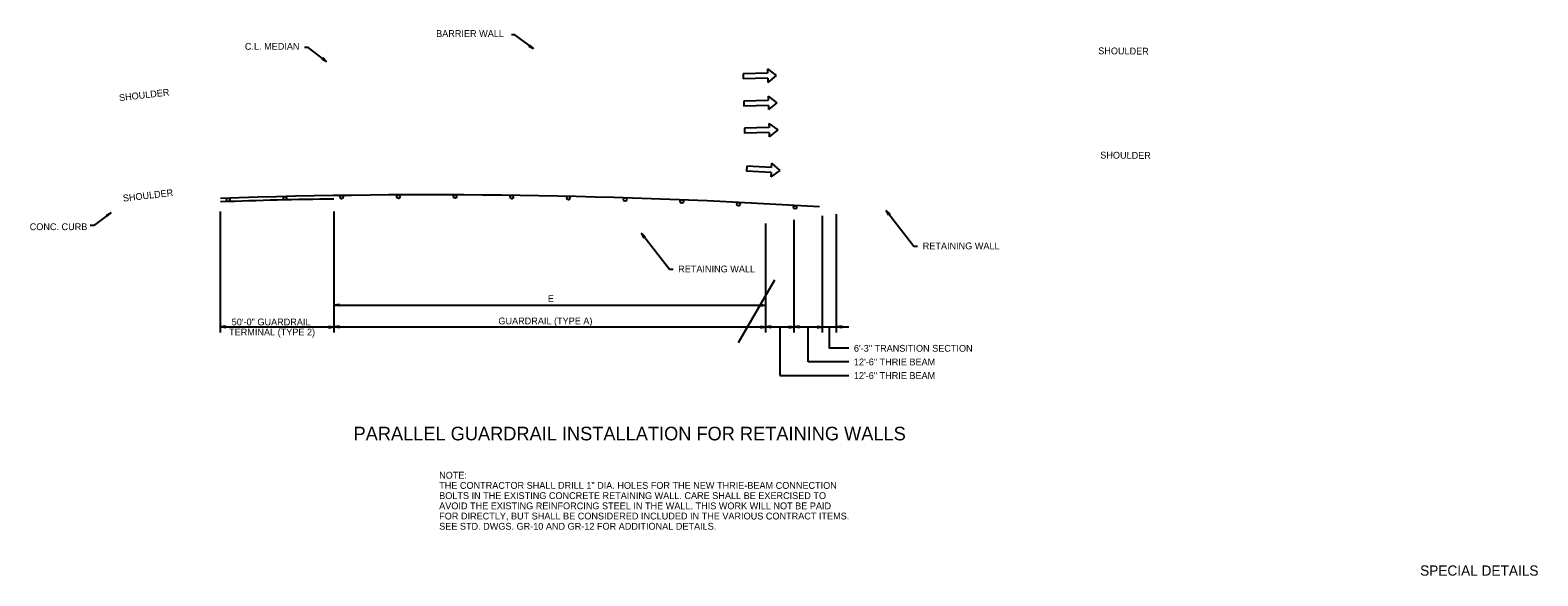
# Model space of a CAD drawing. Extents: x 1373853 to 1374003, y 380191 to 380927.
# Drawn here: x 1373870.3 to 1374003.2, y 380509.2 to 380557.2 of the extents above; entities that cross this region are included whole.
import ezdxf

# ---------------------------------------------------------------- set-up
doc = ezdxf.new("R2010")
doc.units = 0
for name, color, linetype in [('2', 7, 'Continuous'), ('7', 7, 'Continuous'), ('8', 7, 'Continuous'), ('Default', 7, 'Continuous'), ('E_Existing ROW', 7, 'Continuous'), ('G-ANNO-TEXT', 7, 'Continuous'), ('R_Proposed Road', 7, 'Continuous')]:
    doc.layers.add(name, color=color, linetype=linetype)

msp = doc.modelspace()

# ---------------------------------------------------------------- linework, layer by layer
at = {"layer": '2'}
for p, q in [((1373913.01, 380556.85), (1373912.7, 380556.85)), ((1373914.64, 380555.62), (1373913.01, 380556.85)), ((1373894.78, 380555.72), (1373894.46, 380555.72)), ((1373896.4, 380554.49), (1373894.78, 380555.72)), ((1373945.73, 380541.37), (1373948.19, 380538.22)), ((1373875.87, 380540.03), (1373875.55, 380540.03)), ((1373877.41, 380541.19), (1373875.87, 380540.03)), ((1373887.06, 380530.62), (1373887.06, 380541.28)), ((1373897.06, 380530.62), (1373897.06, 380541.28)), ((1373935.12, 380530.62), (1373935.12, 380540.21)), ((1373937.62, 380530.62), (1373937.62, 380540.54)), ((1373940.12, 380530.62), (1373940.12, 380540.88)), ((1373941.37, 380530.62), (1373941.37, 380541.05)), ((1373924.17, 380539.35), (1373926.63, 380536.19)), ((1373948.19, 380538.22), (1373948.51, 380538.22)), ((1373926.63, 380536.19), (1373926.95, 380536.19)), ((1373897.06, 380533.02), (1373935.12, 380533.02)), ((1373887.06, 380531.1), (1373897.06, 380531.1)), ((1373897.06, 380531.1), (1373935.12, 380531.1)), ((1373935.12, 380531.1), (1373937.62, 380531.1)), ((1373936.37, 380531.1), (1373936.37, 380526.81)), ((1373937.62, 380531.1), (1373940.12, 380531.1)), ((1373938.87, 380528.02), (1373938.87, 380531.1)), ((1373940.12, 380531.1), (1373941.37, 380531.1)), ((1373941.37, 380531.1), (1373942.45, 380531.1)), ((1373936.37, 380526.81), (1373942.45, 380526.81)), ((1373942.45, 380528.02), (1373938.87, 380528.02))]:
    msp.add_line(p, q, dxfattribs=at)
msp.add_lwpolyline([(1373942.45, 380529.22), (1373940.75, 380529.22), (1373940.75, 380531.1)], dxfattribs=at)
at = {"layer": '7'}
for p, q in [((1373914.22, 380555.85), (1373914.3, 380555.96)), ((1373914.29, 380555.96), (1373914.58, 380555.67)), ((1373914.3, 380555.96), (1373914.64, 380555.62)), ((1373895.98, 380554.72), (1373896.06, 380554.83)), ((1373895.98, 380554.73), (1373896.34, 380554.54)), ((1373895.98, 380554.72), (1373896.4, 380554.49)), ((1373895.99, 380554.74), (1373896.27, 380554.59)), ((1373896, 380554.75), (1373896.21, 380554.63)), ((1373896.01, 380554.77), (1373896.08, 380554.73)), ((1373896.01, 380554.76), (1373896.15, 380554.68)), ((1373896.03, 380554.79), (1373896.08, 380554.73)), ((1373896.04, 380554.8), (1373896.15, 380554.68)), ((1373896.04, 380554.8), (1373896.21, 380554.63)), ((1373896.05, 380554.82), (1373896.34, 380554.54)), ((1373896.05, 380554.81), (1373896.27, 380554.59)), ((1373896.06, 380554.83), (1373896.4, 380554.49)), ((1373914.22, 380555.86), (1373914.58, 380555.67)), ((1373914.22, 380555.85), (1373914.64, 380555.62)), ((1373914.23, 380555.87), (1373914.51, 380555.72)), ((1373914.24, 380555.88), (1373914.45, 380555.76)), ((1373914.25, 380555.9), (1373914.32, 380555.86)), ((1373914.25, 380555.89), (1373914.38, 380555.81)), ((1373914.27, 380555.93), (1373914.38, 380555.81)), ((1373914.27, 380555.92), (1373914.32, 380555.86)), ((1373914.28, 380555.94), (1373914.51, 380555.72)), ((1373914.28, 380555.93), (1373914.45, 380555.76)), ((1373946.08, 380541.04), (1373945.73, 380541.37)), ((1373945.97, 380540.95), (1373945.73, 380541.37)), ((1373876.99, 380540.96), (1373877.41, 380541.19)), ((1373876.99, 380540.95), (1373877.35, 380541.14)), ((1373876.99, 380540.96), (1373877.07, 380540.85)), ((1373877, 380540.94), (1373877.28, 380541.09)), ((1373877.01, 380540.93), (1373877.22, 380541.05)), ((1373877.02, 380540.92), (1373877.15, 380541)), ((1373877.02, 380540.91), (1373877.09, 380540.95)), ((1373877.04, 380540.88), (1373877.15, 380541)), ((1373877.04, 380540.89), (1373877.09, 380540.95)), ((1373877.05, 380540.87), (1373877.28, 380541.09)), ((1373877.05, 380540.88), (1373877.22, 380541.05)), ((1373877.06, 380540.85), (1373877.35, 380541.14)), ((1373877.07, 380540.85), (1373877.41, 380541.19)), ((1373946.07, 380541.03), (1373945.78, 380541.31)), ((1373945.98, 380540.96), (1373945.78, 380541.31)), ((1373945.99, 380540.97), (1373945.83, 380541.25)), ((1373946.06, 380541.03), (1373945.83, 380541.25)), ((1373946.05, 380541.02), (1373945.88, 380541.18)), ((1373946, 380540.98), (1373945.88, 380541.18)), ((1373946, 380540.98), (1373945.92, 380541.12)), ((1373946.04, 380541.01), (1373945.92, 380541.12)), ((1373946.08, 380541.04), (1373945.97, 380540.95)), ((1373946.01, 380540.99), (1373945.98, 380541.06)), ((1373946.03, 380541), (1373945.98, 380541.06)), ((1373924.52, 380539.02), (1373924.17, 380539.35)), ((1373924.41, 380538.93), (1373924.17, 380539.35)), ((1373924.51, 380539.01), (1373924.22, 380539.29)), ((1373924.42, 380538.93), (1373924.22, 380539.29)), ((1373924.43, 380538.94), (1373924.27, 380539.22)), ((1373924.5, 380539), (1373924.27, 380539.22)), ((1373924.49, 380538.99), (1373924.32, 380539.16)), ((1373924.44, 380538.95), (1373924.32, 380539.16)), ((1373924.44, 380538.96), (1373924.37, 380539.1)), ((1373924.48, 380538.99), (1373924.37, 380539.1)), ((1373924.52, 380539.02), (1373924.41, 380538.93)), ((1373924.45, 380538.97), (1373924.42, 380539.03)), ((1373924.47, 380538.98), (1373924.42, 380539.03)), ((1373897.53, 380533.09), (1373897.06, 380533.02)), ((1373897.53, 380532.95), (1373897.06, 380533.02)), ((1373897.53, 380533.08), (1373897.13, 380533.02)), ((1373897.53, 380532.96), (1373897.13, 380533.02)), ((1373897.53, 380533.07), (1373897.22, 380533.02)), ((1373897.53, 380532.97), (1373897.22, 380533.02)), ((1373897.53, 380533.06), (1373897.3, 380533.02)), ((1373897.53, 380532.98), (1373897.3, 380533.02)), ((1373897.53, 380533.04), (1373897.38, 380533.02)), ((1373897.53, 380533), (1373897.38, 380533.02)), ((1373897.53, 380533.03), (1373897.46, 380533.02)), ((1373897.53, 380533.01), (1373897.46, 380533.02)), ((1373897.53, 380532.95), (1373897.53, 380533.09)), ((1373934.64, 380533.09), (1373935.12, 380533.02)), ((1373934.64, 380533.09), (1373934.64, 380532.95)), ((1373934.64, 380533.08), (1373935.04, 380533.02)), ((1373934.64, 380533.07), (1373934.96, 380533.02)), ((1373934.64, 380533.06), (1373934.88, 380533.02)), ((1373934.64, 380533.04), (1373934.8, 380533.02)), ((1373934.64, 380533.03), (1373934.72, 380533.02)), ((1373934.64, 380532.95), (1373935.12, 380533.02)), ((1373934.64, 380533), (1373934.8, 380533.02)), ((1373934.64, 380532.97), (1373934.96, 380533.02)), ((1373934.64, 380532.96), (1373935.04, 380533.02)), ((1373934.64, 380532.98), (1373934.88, 380533.02)), ((1373934.64, 380533.01), (1373934.72, 380533.02)), ((1373887.53, 380531.17), (1373887.06, 380531.1)), ((1373887.53, 380531.02), (1373887.06, 380531.1)), ((1373887.53, 380531.16), (1373887.13, 380531.1)), ((1373887.53, 380531.04), (1373887.13, 380531.1)), ((1373887.53, 380531.14), (1373887.22, 380531.1)), ((1373887.53, 380531.05), (1373887.22, 380531.1)), ((1373887.53, 380531.13), (1373887.3, 380531.1)), ((1373887.53, 380531.06), (1373887.3, 380531.1)), ((1373887.53, 380531.12), (1373887.38, 380531.1)), ((1373887.53, 380531.07), (1373887.38, 380531.1)), ((1373887.53, 380531.11), (1373887.46, 380531.1)), ((1373887.53, 380531.08), (1373887.46, 380531.1)), ((1373887.53, 380531.02), (1373887.53, 380531.17)), ((1373896.58, 380531.17), (1373897.06, 380531.1)), ((1373896.58, 380531.17), (1373896.58, 380531.02)), ((1373896.58, 380531.16), (1373896.97, 380531.1)), ((1373896.58, 380531.14), (1373896.89, 380531.1)), ((1373896.58, 380531.13), (1373896.81, 380531.1)), ((1373896.58, 380531.12), (1373896.73, 380531.1)), ((1373896.58, 380531.11), (1373896.65, 380531.1)), ((1373896.58, 380531.02), (1373897.06, 380531.1)), ((1373896.58, 380531.07), (1373896.73, 380531.1)), ((1373896.58, 380531.05), (1373896.89, 380531.1)), ((1373896.58, 380531.04), (1373896.97, 380531.1)), ((1373896.58, 380531.06), (1373896.81, 380531.1)), ((1373896.58, 380531.08), (1373896.65, 380531.1)), ((1373897.53, 380531.17), (1373897.06, 380531.1)), ((1373897.53, 380531.02), (1373897.06, 380531.1)), ((1373897.53, 380531.16), (1373897.13, 380531.1)), ((1373897.53, 380531.04), (1373897.13, 380531.1)), ((1373897.53, 380531.14), (1373897.22, 380531.1)), ((1373897.53, 380531.05), (1373897.22, 380531.1)), ((1373897.53, 380531.13), (1373897.3, 380531.1)), ((1373897.53, 380531.06), (1373897.3, 380531.1)), ((1373897.53, 380531.12), (1373897.38, 380531.1)), ((1373897.53, 380531.07), (1373897.38, 380531.1)), ((1373897.53, 380531.11), (1373897.46, 380531.1)), ((1373897.53, 380531.08), (1373897.46, 380531.1)), ((1373897.53, 380531.02), (1373897.53, 380531.17)), ((1373934.65, 380531.17), (1373935.12, 380531.1)), ((1373934.65, 380531.02), (1373934.65, 380531.17)), ((1373934.65, 380531.16), (1373935.04, 380531.1)), ((1373934.65, 380531.14), (1373934.96, 380531.1)), ((1373934.65, 380531.13), (1373934.88, 380531.1)), ((1373934.65, 380531.12), (1373934.8, 380531.1)), ((1373934.65, 380531.11), (1373934.72, 380531.1)), ((1373934.65, 380531.02), (1373935.12, 380531.1)), ((1373934.65, 380531.07), (1373934.8, 380531.1)), ((1373934.65, 380531.05), (1373934.96, 380531.1)), ((1373934.65, 380531.04), (1373935.04, 380531.1)), ((1373934.65, 380531.06), (1373934.88, 380531.1)), ((1373934.65, 380531.08), (1373934.72, 380531.1)), ((1373935.6, 380531.17), (1373935.12, 380531.1)), ((1373935.6, 380531.02), (1373935.12, 380531.1)), ((1373935.6, 380531.16), (1373935.2, 380531.1)), ((1373935.6, 380531.04), (1373935.2, 380531.1)), ((1373935.6, 380531.14), (1373935.29, 380531.1)), ((1373935.6, 380531.05), (1373935.29, 380531.1)), ((1373935.6, 380531.13), (1373935.37, 380531.1)), ((1373935.6, 380531.06), (1373935.37, 380531.1)), ((1373935.6, 380531.12), (1373935.45, 380531.1)), ((1373935.6, 380531.07), (1373935.45, 380531.1)), ((1373935.6, 380531.11), (1373935.53, 380531.1)), ((1373935.6, 380531.08), (1373935.53, 380531.1)), ((1373935.6, 380531.02), (1373935.6, 380531.17)), ((1373937.15, 380531.17), (1373937.62, 380531.1)), ((1373937.15, 380531.02), (1373937.15, 380531.17)), ((1373937.15, 380531.16), (1373937.54, 380531.1)), ((1373937.15, 380531.14), (1373937.46, 380531.1)), ((1373937.15, 380531.13), (1373937.38, 380531.1)), ((1373937.15, 380531.12), (1373937.3, 380531.1)), ((1373937.15, 380531.11), (1373937.22, 380531.1)), ((1373937.15, 380531.02), (1373937.62, 380531.1)), ((1373937.15, 380531.07), (1373937.3, 380531.1)), ((1373937.15, 380531.05), (1373937.46, 380531.1)), ((1373937.15, 380531.04), (1373937.54, 380531.1)), ((1373937.15, 380531.06), (1373937.38, 380531.1)), ((1373937.15, 380531.08), (1373937.22, 380531.1)), ((1373938.1, 380531.17), (1373937.62, 380531.1)), ((1373938.1, 380531.02), (1373937.62, 380531.1)), ((1373938.1, 380531.16), (1373937.7, 380531.1)), ((1373938.1, 380531.04), (1373937.7, 380531.1)), ((1373938.1, 380531.14), (1373937.79, 380531.1)), ((1373938.1, 380531.05), (1373937.79, 380531.1)), ((1373938.1, 380531.13), (1373937.87, 380531.1)), ((1373938.1, 380531.06), (1373937.87, 380531.1)), ((1373938.1, 380531.12), (1373937.95, 380531.1)), ((1373938.1, 380531.07), (1373937.95, 380531.1)), ((1373938.1, 380531.11), (1373938.03, 380531.1)), ((1373938.1, 380531.08), (1373938.03, 380531.1)), ((1373938.1, 380531.02), (1373938.1, 380531.17)), ((1373939.65, 380531.17), (1373940.12, 380531.1)), ((1373939.65, 380531.02), (1373939.65, 380531.17)), ((1373939.65, 380531.16), (1373940.04, 380531.1)), ((1373939.65, 380531.14), (1373939.96, 380531.1)), ((1373939.65, 380531.13), (1373939.88, 380531.1)), ((1373939.65, 380531.12), (1373939.8, 380531.1)), ((1373939.65, 380531.11), (1373939.72, 380531.1)), ((1373939.65, 380531.02), (1373940.12, 380531.1)), ((1373939.65, 380531.07), (1373939.8, 380531.1)), ((1373939.65, 380531.05), (1373939.96, 380531.1)), ((1373939.65, 380531.04), (1373940.04, 380531.1)), ((1373939.65, 380531.06), (1373939.88, 380531.1)), ((1373939.65, 380531.08), (1373939.72, 380531.1)), ((1373941.85, 380531.17), (1373941.37, 380531.1)), ((1373941.85, 380531.02), (1373941.37, 380531.1)), ((1373941.85, 380531.16), (1373941.45, 380531.1)), ((1373941.85, 380531.04), (1373941.45, 380531.1)), ((1373941.85, 380531.14), (1373941.54, 380531.1)), ((1373941.85, 380531.05), (1373941.54, 380531.1)), ((1373941.85, 380531.13), (1373941.62, 380531.1)), ((1373941.85, 380531.06), (1373941.62, 380531.1)), ((1373941.85, 380531.12), (1373941.7, 380531.1)), ((1373941.85, 380531.07), (1373941.7, 380531.1)), ((1373941.85, 380531.11), (1373941.78, 380531.1)), ((1373941.85, 380531.08), (1373941.78, 380531.1)), ((1373941.85, 380531.02), (1373941.85, 380531.17))]:
    msp.add_line(p, q, dxfattribs=at)
at = {"layer": 'Default'}
for p, q in [((1373935.28, 380553.46), (1373933.12, 380553.4)), ((1373933.12, 380553.4), (1373933.13, 380552.96)), ((1373935.27, 380553.83), (1373935.28, 380553.46)), ((1373935.27, 380553.83), (1373936.05, 380553.26)), ((1373935.29, 380553.02), (1373933.13, 380552.96)), ((1373935.29, 380553.02), (1373935.3, 380552.65)), ((1373936.05, 380553.26), (1373935.3, 380552.65)), ((1373935.34, 380551.06), (1373933.18, 380551)), ((1373933.18, 380551), (1373933.2, 380550.56)), ((1373935.33, 380551.43), (1373935.34, 380551.06)), ((1373935.33, 380551.43), (1373936.11, 380550.86)), ((1373936.11, 380550.86), (1373935.37, 380550.25)), ((1373935.36, 380550.62), (1373933.2, 380550.56)), ((1373935.36, 380550.62), (1373935.37, 380550.25)), ((1373935.41, 380548.66), (1373933.25, 380548.6)), ((1373933.25, 380548.6), (1373933.26, 380548.16)), ((1373935.42, 380548.22), (1373933.26, 380548.16)), ((1373935.4, 380549.03), (1373935.41, 380548.66)), ((1373935.4, 380549.03), (1373936.18, 380548.46)), ((1373935.42, 380548.22), (1373935.43, 380547.85)), ((1373936.18, 380548.46), (1373935.43, 380547.85)), ((1373935.63, 380545.52), (1373935.61, 380545.15)), ((1373935.63, 380545.52), (1373936.36, 380544.89)), ((1373933.45, 380545.26), (1373933.43, 380544.82)), ((1373935.59, 380544.71), (1373933.43, 380544.82)), ((1373935.61, 380545.15), (1373933.45, 380545.26)), ((1373936.36, 380544.89), (1373935.57, 380544.34)), ((1373935.59, 380544.71), (1373935.57, 380544.34))]:
    msp.add_line(p, q, dxfattribs=at)
at = {"layer": 'E_Existing ROW'}
msp.add_lwpolyline([(1373932.73, 380529.72), (1373935.92, 380535.25)], dxfattribs=at)
msp.add_lwpolyline([(1373932.73, 380529.72), (1373935.92, 380535.25)], dxfattribs=at)
at = {"layer": 'R_Proposed Road'}
for centre in [(1373897.73, 380542.54), (1373902.73, 380542.58), (1373907.73, 380542.59), (1373912.73, 380542.55), (1373887.73, 380542.3), (1373892.73, 380542.44), (1373917.72, 380542.46), (1373922.72, 380542.33), (1373927.72, 380542.15), (1373932.71, 380541.92), (1373937.71, 380541.65)]:
    msp.add_circle(centre, 0.15, dxfattribs=at)
for radius, start in [(548.45, 86.4203), (548.15, 90.8956)]:
    msp.add_arc((1373905.62, 379994.29), radius, start, 91.9409, dxfattribs=at)

# ---------------------------------------------------------------- texts
at = {"layer": '2'}
for s, rotation, p in [('C.L. MEDIAN', 0, (1373889.2, 380555.52)), ('BARRIER WALL', 0, (1373906.06, 380556.65)), ('SHOULDER', 359.5475, (1373964.43, 380555.13)), ('SHOULDER', 6.5132, (1373878.14, 380550.99)), ('SHOULDER', 359.5475, (1373964.61, 380545.94)), ('SHOULDER', 6.5724, (1373878.48, 380542.14)), ('CONC. CURB', 360, (1373870.23, 380539.63)), ('RETAINING WALL', 0, (1373948.96, 380537.94)), ('RETAINING WALL', 0, (1373927.4, 380535.91)), ('E', 0, (1373915.91, 380533.3)), ('TERMINAL (TYPE 2)', 0, (1373887.81, 380530.35)), ('50\'-0" GUARDRAIL', 0, (1373888.04, 380531.24)), ('GUARDRAIL (TYPE A)', 0, (1373911.55, 380531.33)), ('6\'-3" TRANSITION SECTION', 0, (1373942.89, 380528.92)), ('12\'-6" THRIE BEAM', 0, (1373942.89, 380527.72)), ('12\'-6" THRIE BEAM', 0, (1373942.89, 380526.52)), ('THE CONTRACTOR SHALL DRILL 1" DIA. HOLES FOR THE NEW THRIE-BEAM CONNECTION', 0, (1373906.33, 380516.84)), ('NOTE:', 0, (1373906.33, 380517.74)), ('BOLTS IN THE EXISTING CONCRETE RETAINING WALL. CARE SHALL BE EXERCISED TO', 0, (1373906.33, 380515.94)), ('AVOID THE EXISTING REINFORCING STEEL IN THE WALL. THIS WORK WILL NOT BE PAID', 0, (1373906.33, 380515.04)), ('FOR DIRECTLY, BUT SHALL BE CONSIDERED INCLUDED IN THE VARIOUS CONTRACT ITEMS.', 0, (1373906.33, 380514.14)), ('SEE STD. DWGS. GR-10 AND GR-12 FOR ADDITIONAL DETAILS.', 0, (1373906.33, 380513.24))]:
    msp.add_text(s, height=0.6, rotation=rotation, dxfattribs=at).set_placement(p)
at = {"layer": '8'}
msp.add_text('PARALLEL GUARDRAIL INSTALLATION FOR RETAINING WALLS', height=1.2, rotation=0, dxfattribs=at).set_placement((1373898.78, 380521.11))
at = {"layer": 'G-ANNO-TEXT'}
msp.add_text('SPECIAL DETAILS', height=0.9, dxfattribs=at).set_placement((1373992.81, 380509.19))

doc.saveas('drawing.dxf')
